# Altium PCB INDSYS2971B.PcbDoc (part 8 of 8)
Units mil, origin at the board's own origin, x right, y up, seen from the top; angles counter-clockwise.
Board outline 6450 x 5820 mil, 6 copper layers (Top Layer, Int1 (PGND), Int2 (AGND), Int3 (Signal), Int4 (PGND), Bottom Layer), stack 70.536 mil thick; 787 components, 431 nets, 2530 pads, 2497 vias.
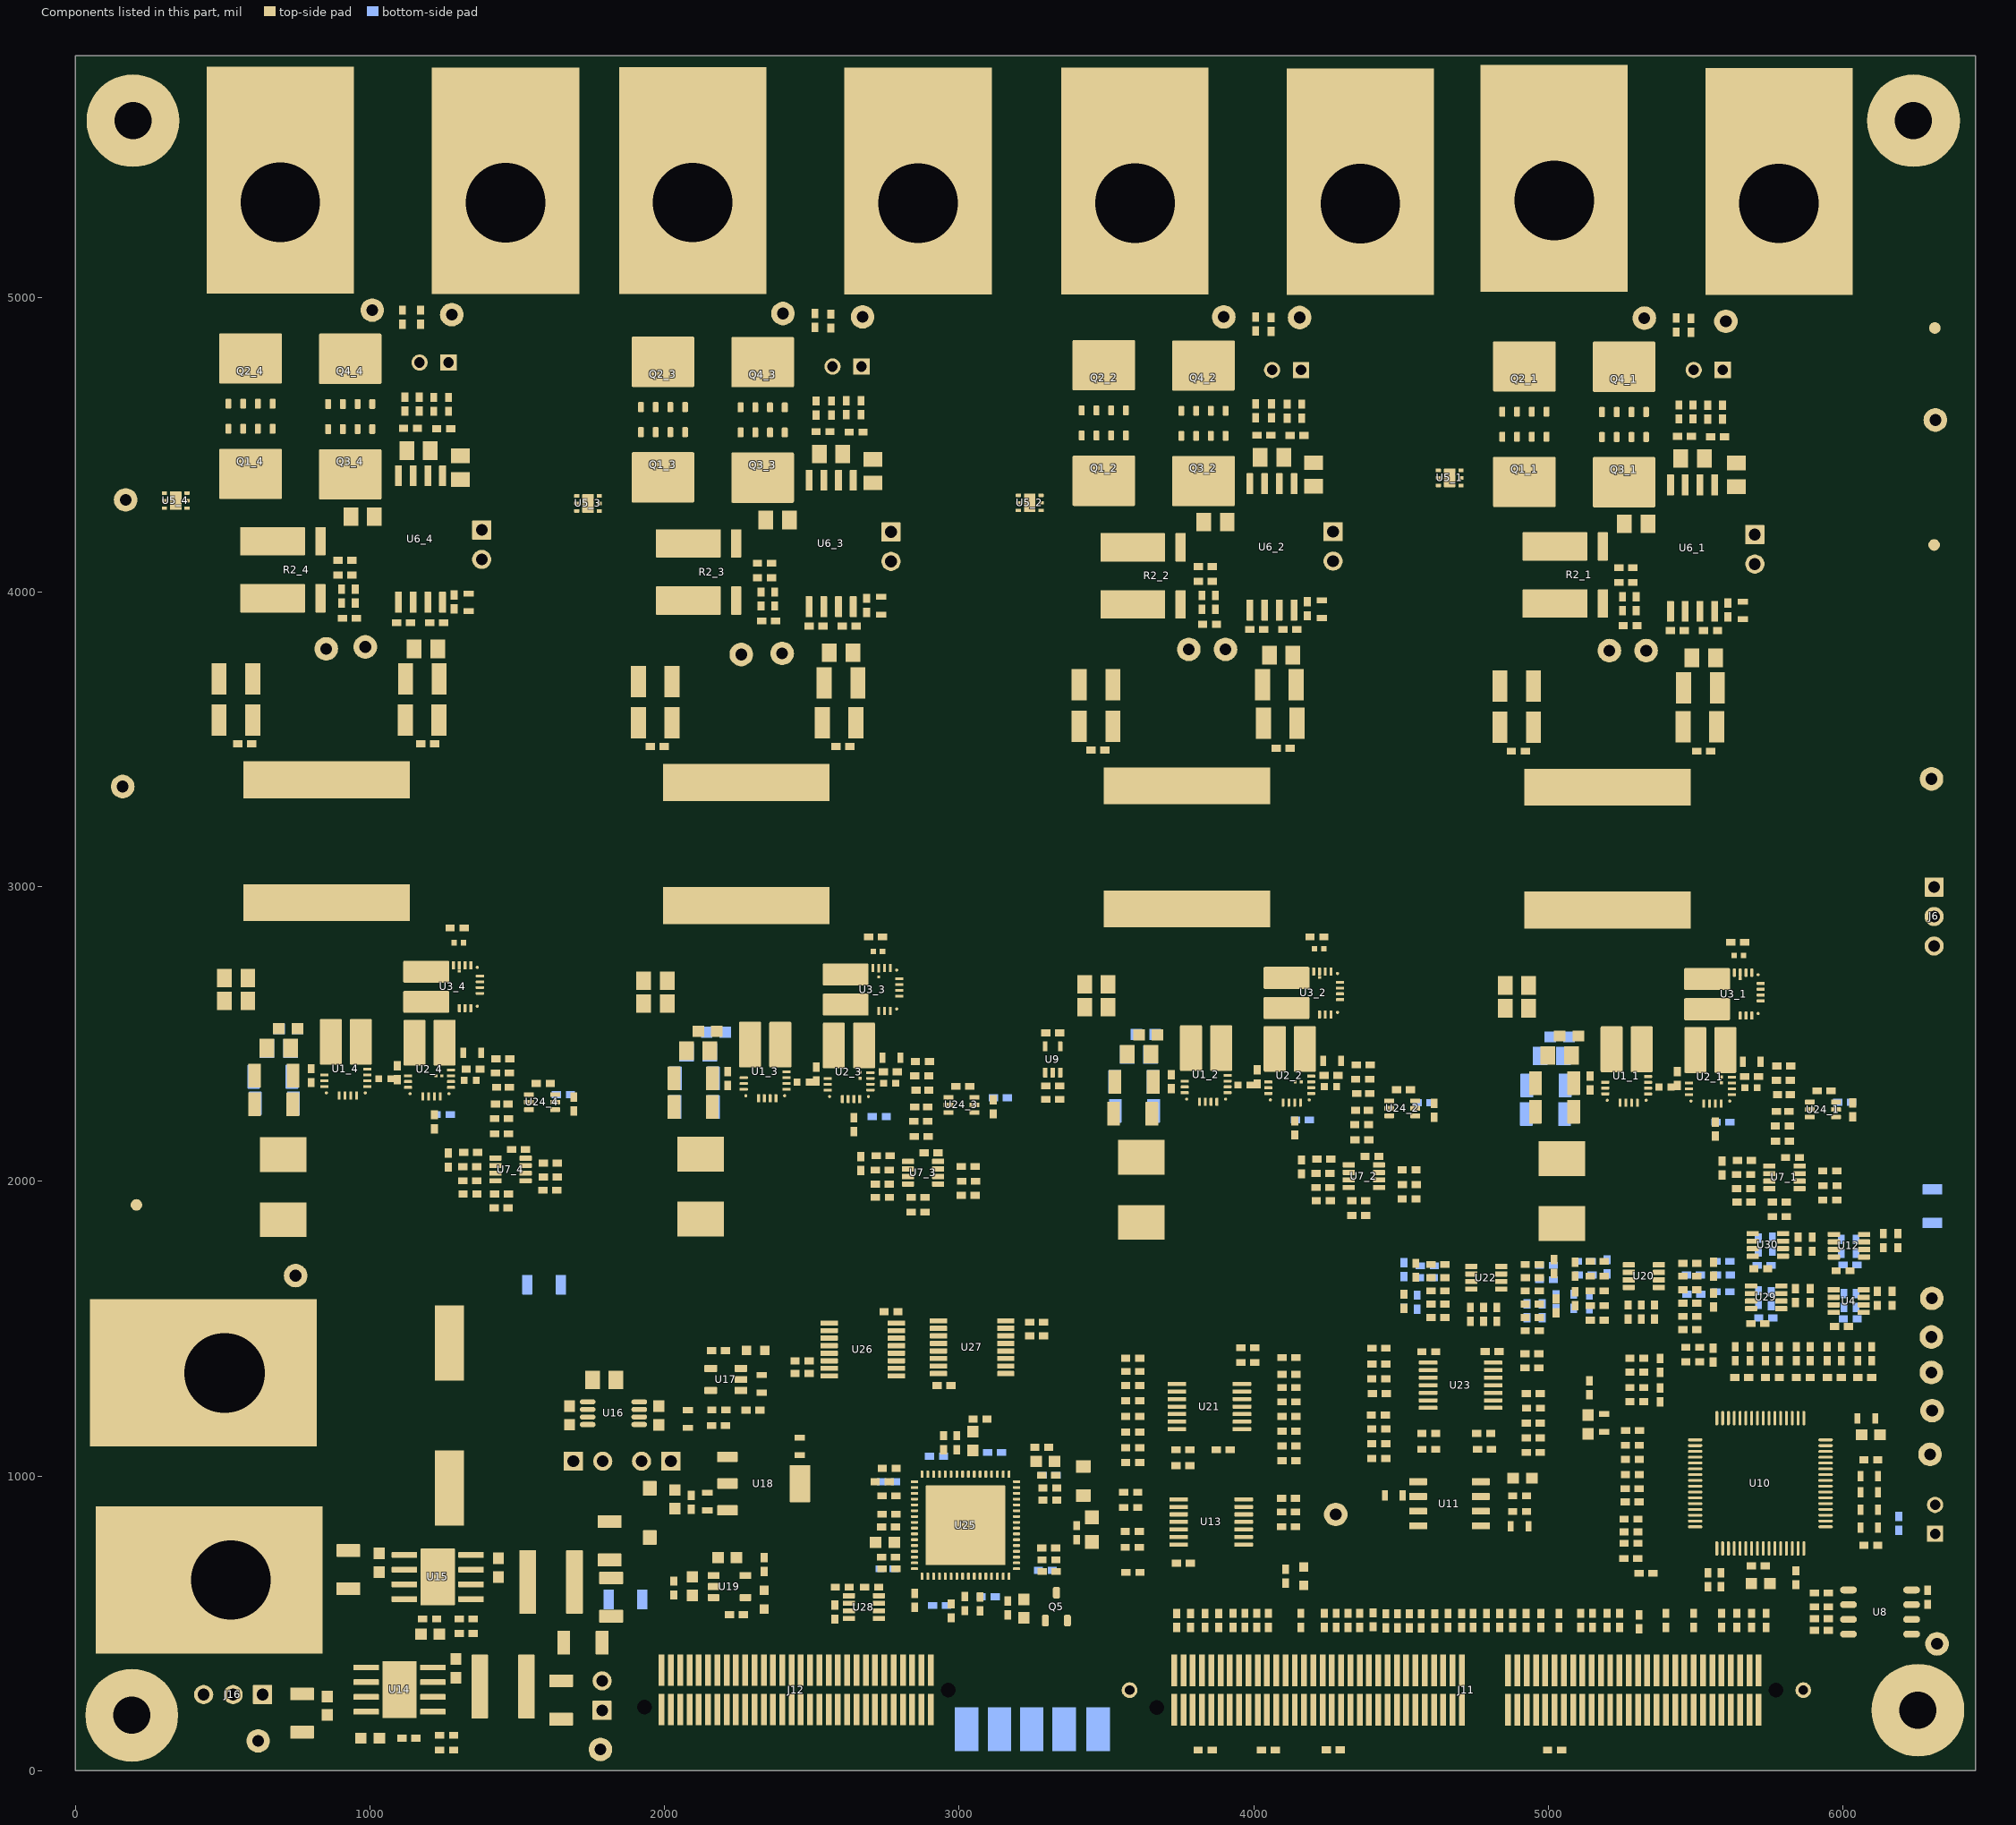
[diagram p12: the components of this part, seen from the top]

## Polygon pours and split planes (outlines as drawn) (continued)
V_HV_3 on Top Layer "TOP_LAYER_V_HV_3_P382" (solid, remove dead copper, pour order 382): 25 vertices, not listed, extent 1778.93,1945.87 2593.62,2540.85
Source_3 on Top Layer "TOP_LAYER_SOURCE_3_P397" (solid, remove dead copper, pour order 397): 1775.39,4685.87 2440.84,4685.87 2440.84,4491.54 1775.39,4491.54
BATP_3 on Top Layer "TOP_LAYER_BATP_3_P400" (solid, remove dead copper, pour order 400): 2455.39,4695.87 1775.39,4695.87 1775.39,5784.26 2455.39,5784.26
SW_2 on Top Layer "TOP_LAYER_SW_2_P380" (solid, remove dead copper, pour order 380): 23 vertices, not listed, extent 3275.54,2344.14 4211.89,3185.33
V_HV_2 on Top Layer "TOP_LAYER_V_HV_2_P384" (solid, remove dead copper, pour order 384): 25 vertices, not listed, extent 3275.54,1934.14 4090.23,2529.12
NetC11_2_1 on Top Layer "TOP_LAYER_NETC11_2_1_P389" (solid, remove dead copper, pour order 389): 3761.01,4033.91 3761.01,3833 4102.11,3833 4102.11,3717.11 4102.11,3193 3275.54,3193 3275.54,3423 3461.42,3423 3481.62,3443.2 3481.62,3747.29 3275.54,3747.29 3275.54,4033.91
Source_2 on Top Layer "TOP_LAYER_SOURCE_2_P398" (solid, remove dead copper, pour order 398): 3272,4674.14 3937.44,4674.14 3937.44,4479.81 3272,4479.81
BATP_2 on Top Layer "TOP_LAYER_BATP_2_P403" (solid, remove dead copper, pour order 403): 3952,4684.14 3272,4684.14 3272,5772.53 3952,5772.53
OUTP2 on Top Layer "TOP_LAYER_OUTP2_P394" (solid, remove dead copper, pour order 394): 3734.05,4197.88 3882.13,4197.88 3884.05,4207.13 3882.13,4207.9 3882.13,4467.75 3877.13,4472.75 3272,4472.75 3272,4047.75 3734.05,4047.75
OUTP1 on Top Layer "TOP_LAYER_OUTP1_P390" (solid, remove dead copper, pour order 390): 5162.05,4193.88 5310.13,4193.88 5312.05,4203.13 5310.13,4203.9 5310.13,4463.75 5305.13,4468.75 4700,4468.75 4700,4043.75 5162.05,4043.75
BATP_1 on Top Layer "TOP_LAYER_BATP_1_P399" (solid, remove dead copper, pour order 399): 5380,4680.14 4700,4680.14 4700,5768.53 5380,5768.53
NetC11_1_1 on Top Layer "TOP_LAYER_NETC11_1_1_P385" (solid, remove dead copper, pour order 385): 5189.01,4029.91 5189.01,3829 5530.11,3829 5530.11,3713.11 5530.11,3189 4703.54,3189 4703.54,3419 4889.42,3419 4909.62,3439.2 4909.62,3743.29 4703.54,3743.29 4703.54,4029.91
V_HV_1 on Top Layer "TOP_LAYER_V_HV_1_P381" (solid, remove dead copper, pour order 381): 25 vertices, not listed, extent 4703.54,1930.14 5518.23,2525.12
SW_1 on Top Layer "TOP_LAYER_SW_1_P377" (solid, remove dead copper, pour order 377): 23 vertices, not listed, extent 4700,2332.76 5636.35,3173.94
NetC11_3_1 on Bottom Layer "BOTTOM_LAYER_NETC11_3_1_P409" (solid, remove dead copper, pour order 409): 2263.78,4046.26 2263.78,3845.35 2604.88,3845.35 2604.88,3729.46 2604.88,3205.35 1778.31,3205.35 1778.31,3435.35 1964.19,3435.35 1984.39,3455.55 1984.39,3759.64 1778.31,3759.64 1778.31,4046.26
AGND on Bottom Layer "BOTTOM_LAYER_AGND_P498" (solid, remove dead copper, pour order 498): 1571.84,39.35 1571.84,71.66 1571.84,1929.41 6350.52,1929.41 6380,1899.93 6380,50.14
5VA on Bottom Layer "BOTTOM_LAYER_5VA_P410" (solid, remove dead copper, pour order 410): 2513.03,647.11 2546.26,613.88 2682.91,613.88 2682.91,687.39 2708.21,687.39 2708.21,555.14 2665,511.93 2665,511.52 2585.82,511.52 2547.2,550.14 2513.03,550.14
AGND on Bottom Layer "BOTTOM_LAYER_AGND_P500" (solid, remove dead copper, pour order 500): 1571.84,39.35 1571.84,71.66 1571.84,1929.41 6350.52,1929.41 6380,1899.93 6380,50.14
PGND on Bottom Layer "BOTTOM_LAYER_PGND_P499" (solid, remove dead copper, pour order 499): 42.17,40.14 1862.17,40.14 1862.17,927.04 1830.13,959.08 1631.15,959.08 1588.55,1001.68 1592.89,1006.03 1592.89,1902.34 6399.97,1902.34 6401.97,1900.35 6401.97,5770.82 42.84,5770.82 42.17,5770.14
PGND on Bottom Layer "BOTTOM_LAYER_PGND_P427" (solid, remove dead copper, pour order 427): 18 vertices, not listed, extent 1056.38,2331.49 1676.69,5779.54
PGND on Bottom Layer "BOTTOM_LAYER_PGND_P426" (solid, remove dead copper, pour order 426): 18 vertices, not listed, extent 5405,2306.49 6025.31,5754.54
OUTP1 on Bottom Layer "BOTTOM_LAYER_OUTP1_P437" (solid, remove dead copper, pour order 437): 5148.25,4188.53 5296.33,4188.53 5296.33,4188.66 5301.34,4193.67 5296.33,4198.69 5296.33,4458.53 5291.33,4463.53 4696.2,4463.53 4696.2,4038.53 5148.25,4038.53
OUTP3 on Bottom Layer "BOTTOM_LAYER_OUTP3_P435" (solid, remove dead copper, pour order 435): 2283.64,4204.14 2431.72,4204.14 2431.72,4204.27 2436.73,4209.28 2431.72,4214.29 2431.72,4474.14 2426.72,4479.14 1831.59,4479.14 1831.59,4054.14 2283.64,4054.14
PGND on Bottom Layer "BOTTOM_LAYER_PGND_P425" (solid, remove dead copper, pour order 425): 18 vertices, not listed, extent 2540.39,2322.1 3160.71,5770.14
PGND on Bottom Layer "BOTTOM_LAYER_PGND_P428" (solid, remove dead copper, pour order 428): 18 vertices, not listed, extent 3931.8,2335.49 4552.12,5783.54
V_HV_2 on Bottom Layer "BOTTOM_LAYER_V_HV_2_P494" (solid, remove dead copper, pour order 494): 25 vertices, not listed, extent 3275.54,1932.73 4090.23,2527.71
NetC11_4_1 on Bottom Layer "BOTTOM_LAYER_NETC11_4_1_P417" (solid, remove dead copper, pour order 417): 863.73,4048.07 863.73,3847.16 1164.9,3847.16 1164.9,3207.16 378.25,3207.16 378.25,3437.16 564.14,3437.16 584.34,3457.36 584.34,3761.45 378.25,3761.45 378.25,4048.07
V_HV_4 on Bottom Layer "BOTTOM_LAYER_V_HV_4_P491" (solid, remove dead copper, pour order 491): 25 vertices, not listed, extent 372.33,1945.13 1187.02,2540.11
OUTP4 on Bottom Layer "BOTTOM_LAYER_OUTP4_P438" (solid, remove dead copper, pour order 438): 823.25,4213.53 971.33,4213.53 971.33,4213.66 976.34,4218.67 971.33,4223.69 971.33,4483.53 966.33,4488.53 371.2,4488.53 371.2,4063.53 823.25,4063.53
Source_4 on Bottom Layer "BOTTOM_LAYER_SOURCE_4_P432" (solid, remove dead copper, pour order 432): 371.2,4682.48 1026.64,4682.48 1026.64,4511.84 371.2,4511.84
BATP_4 on Bottom Layer "BOTTOM_LAYER_BATP_4_P423" (solid, remove dead copper, pour order 423): 1051.2,4692.16 371.2,4692.16 371.2,5782.95 1051.2,5782.95
SW_4 on Bottom Layer "BOTTOM_LAYER_SW_4_P414" (solid, remove dead copper, pour order 414): 23 vertices, not listed, extent 372.33,2354.48 1308.68,3195.66
NetC11_1_1 on Bottom Layer "BOTTOM_LAYER_NETC11_1_1_P418" (solid, remove dead copper, pour order 418): 5188.73,4023.07 5188.73,3822.16 5489.9,3822.16 5489.9,3182.16 4703.25,3182.16 4703.25,3412.16 4889.14,3412.16 4909.34,3432.36 4909.34,3736.45 4703.25,3736.45 4703.25,4023.07
Source_3 on Bottom Layer "BOTTOM_LAYER_SOURCE_3_P431" (solid, remove dead copper, pour order 431): 4696.2,4657.48 5351.64,4657.48 5351.64,4486.84 4696.2,4486.84
BATP_3 on Bottom Layer "BOTTOM_LAYER_BATP_3_P422" (solid, remove dead copper, pour order 422): 5376.2,4667.16 4696.2,4667.16 4696.2,5757.95 5376.2,5757.95
SW_3 on Bottom Layer "BOTTOM_LAYER_SW_3_P412" (solid, remove dead copper, pour order 412): 23 vertices, not listed, extent 1832.72,2345.09 2769.07,3186.27
BATP_3 on Bottom Layer "BOTTOM_LAYER_BATP_3_P421" (solid, remove dead copper, pour order 421): 2511.59,4682.77 1831.59,4682.77 1831.59,5773.55 2511.59,5773.55
Source_3 on Bottom Layer "BOTTOM_LAYER_SOURCE_3_P430" (solid, remove dead copper, pour order 430): 1831.59,4673.09 2487.03,4673.09 2487.03,4502.45 1831.59,4502.45
V_HV_3 on Bottom Layer "BOTTOM_LAYER_V_HV_3_P490" (solid, remove dead copper, pour order 490): 25 vertices, not listed, extent 1785.04,1948.12 2599.73,2543.1
SW_2 on Bottom Layer "BOTTOM_LAYER_SW_2_P415" (solid, remove dead copper, pour order 415): 23 vertices, not listed, extent 3275,2348.94 4211.35,3190.12
BATP_2 on Bottom Layer "BOTTOM_LAYER_BATP_2_P424" (solid, remove dead copper, pour order 424): 3940,4689.47 3260,4689.47 3260,5777.85 3940,5777.85
Source_2 on Bottom Layer "BOTTOM_LAYER_SOURCE_2_P434" (solid, remove dead copper, pour order 434): 3275,4665.47 3930.44,4665.47 3930.44,4494.82 3275,4494.82
OUTP2 on Bottom Layer "BOTTOM_LAYER_OUTP2_P439" (solid, remove dead copper, pour order 439): 3727.05,4197.64 3875.13,4197.64 3875.13,4197.77 3880.15,4202.79 3875.13,4207.8 3875.13,4467.64 3870.13,4472.64 3275,4472.64 3275,4047.64 3727.05,4047.64
NetC11_2_1 on Bottom Layer "BOTTOM_LAYER_NETC11_2_1_P419" (solid, remove dead copper, pour order 419): 3760.48,4043.46 3760.48,3842.54 4061.64,3842.54 4061.64,3202.54 3275,3202.54 3275,3432.54 3460.89,3432.54 3481.09,3452.75 3481.09,3756.83 3275,3756.83 3275,4043.46
V_HV_1 on Bottom Layer "BOTTOM_LAYER_V_HV_1_P454" (solid, remove dead copper, pour order 454): 25 vertices, not listed, extent 4706.13,1928.12 5520.83,2523.1
Source_1 on Bottom Layer "BOTTOM_LAYER_SOURCE_1_P429" (solid, remove dead copper, pour order 429): 4705,4665.47 5360.44,4665.47 5360.44,4494.82 4705,4494.82
BATP_1 on Bottom Layer "BOTTOM_LAYER_BATP_1_P420" (solid, remove dead copper, pour order 420): 5385,4675.14 4705,4675.14 4705,5765.93 5385,5765.93
SW_1 on Bottom Layer "BOTTOM_LAYER_SW_1_P411" (solid, remove dead copper, pour order 411): 23 vertices, not listed, extent 4712.06,2334.45 5648.41,3175.64
AGND on Int2 (AGND) "INT2_(AGND)_AGND_P478" (solid, remove dead copper, pour order 478): 70,50.14 70,5779.54 6399.39,5779.54 6400,5780.14 6400,50.14
V_HV_3 on Int2 (AGND) "INT2_(AGND)_V_HV_3_P470" (solid, remove dead copper, pour order 470): 25 vertices, not listed, extent 1787.89,1945.87 2602.58,2540.85
V_HV_4 on Int2 (AGND) "INT2_(AGND)_V_HV_4_P379" (solid, remove dead copper, pour order 379): 25 vertices, not listed, extent 378.54,1955.27 1193.23,2550.24
SW_4 on Int2 (AGND) "INT2_(AGND)_SW_4_P375" (solid, remove dead copper, pour order 375): 23 vertices, not listed, extent 378.54,2365.27 1314.89,3206.45
SW_3 on Int2 (AGND) "INT2_(AGND)_SW_3_P459" (solid, remove dead copper, pour order 459): 23 vertices, not listed, extent 1778.93,2353.16 2715.28,3194.35
V_HV_2 on Int2 (AGND) "INT2_(AGND)_V_HV_2_P455" (solid, remove dead copper, pour order 455): 25 vertices, not listed, extent 3277.5,1933.74 4092.2,2528.72
SW_2 on Int2 (AGND) "INT2_(AGND)_SW_2_P449" (solid, remove dead copper, pour order 449): 23 vertices, not listed, extent 3275.54,2345.23 4211.89,3186.42
V_HV_1 on Int2 (AGND) "INT2_(AGND)_V_HV_1_P446" (solid, remove dead copper, pour order 446): 25 vertices, not listed, extent 4710,1938.12 5524.69,2533.1
SW_1 on Int2 (AGND) "INT2_(AGND)_SW_1_P444" (solid, remove dead copper, pour order 444): 23 vertices, not listed, extent 4700,2328.96 5636.35,3170.14
V_HV_3 on Int3 (Signal) "INT3_(SIGNAL)_V_HV_3_P469" (solid, remove dead copper, pour order 469): 25 vertices, not listed, extent 1787.89,1943.03 2602.58,2538.01
V_HV_4 on Int3 (Signal) "INT3_(SIGNAL)_V_HV_4_P466" (solid, remove dead copper, pour order 466): 25 vertices, not listed, extent 378.54,1956.52 1193.23,2551.49
SW_4 on Int3 (Signal) "INT3_(SIGNAL)_SW_4_P461" (solid, remove dead copper, pour order 461): 23 vertices, not listed, extent 378.54,2355.27 1314.89,3196.45
SW_3 on Int3 (Signal) "INT3_(SIGNAL)_SW_3_P458" (solid, remove dead copper, pour order 458): 23 vertices, not listed, extent 1778.93,2356.25 2715.28,3197.44
V_HV_2 on Int3 (Signal) "INT3_(SIGNAL)_V_HV_2_P453" (solid, remove dead copper, pour order 453): 25 vertices, not listed, extent 3277.5,1934.14 4092.2,2529.12
SW_2 on Int3 (Signal) "INT3_(SIGNAL)_SW_2_P450" (solid, remove dead copper, pour order 450): 23 vertices, not listed, extent 3265.54,2345.23 4201.89,3186.42
V_HV_1 on Int3 (Signal) "INT3_(SIGNAL)_V_HV_1_P445" (solid, remove dead copper, pour order 445): 25 vertices, not listed, extent 4705.04,1935.8 5519.73,2530.78
SW_1 on Int3 (Signal) "INT3_(SIGNAL)_SW_1_P443" (solid, remove dead copper, pour order 443): 23 vertices, not listed, extent 4700,2328.92 5636.35,3170.1
AGND on Int4 (PGND) "INT4_(PGND)_AGND_P492" (solid, remove dead copper, pour order 492): 1578.15,37.52 1578.15,69.83 1578.15,1927.58 6356.83,1927.58 6386.31,1898.1 6386.31,48.31
PGND on Int4 (PGND) "INT4_(PGND)_PGND_P489" (solid, remove dead copper, pour order 489): 17 vertices, not listed, extent 40,39.35 6399.8,5770.02
Source_1 on Int4 (PGND) "INT4_(PGND)_SOURCE_1_P395" (solid, remove dead copper, pour order 395): 4700,4670.27 5365.44,4670.27 5365.44,4475.94 4700,4475.94
Source_2 on Int4 (PGND) "INT4_(PGND)_SOURCE_2_P483" (solid, remove dead copper, pour order 483): 3272.39,4681.15 3937.83,4681.15 3937.83,4486.82 3272.39,4486.82
Source_3 on Int4 (PGND) "INT4_(PGND)_SOURCE_3_P482" (solid, remove dead copper, pour order 482): 1780.39,4689 2445.84,4689 2445.84,4494.67 1780.39,4494.67
Source_4 on Int4 (PGND) "INT4_(PGND)_SOURCE_4_P396" (solid, remove dead copper, pour order 396): 375,4695.27 1040.44,4695.27 1040.44,4500.94 375,4500.94
V_HV_3 on Int4 (PGND) "INT4_(PGND)_V_HV_3_P471" (solid, remove dead copper, pour order 471): 25 vertices, not listed, extent 1778.93,1948.47 2593.62,2543.45
V_HV_4 on Int4 (PGND) "INT4_(PGND)_V_HV_4_P465" (solid, remove dead copper, pour order 465): 25 vertices, not listed, extent 378.54,1955.85 1193.23,2550.82
SW_4 on Int4 (PGND) "INT4_(PGND)_SW_4_P460" (solid, remove dead copper, pour order 460): 23 vertices, not listed, extent 385.22,2352.61 1321.57,3193.8
SW_3 on Int4 (PGND) "INT4_(PGND)_SW_3_P457" (solid, remove dead copper, pour order 457): 23 vertices, not listed, extent 1778.93,2356.25 2715.28,3197.44
V_HV_2 on Int4 (PGND) "INT4_(PGND)_V_HV_2_P440" (solid, remove dead copper, pour order 440): 25 vertices, not listed, extent 3275,1944.13 4089.69,2539.11
SW_2 on Int4 (PGND) "INT4_(PGND)_SW_2_P451" (solid, remove dead copper, pour order 451): 23 vertices, not listed, extent 3265.54,2345.23 4201.89,3186.42
V_HV_1 on Int4 (PGND) "INT4_(PGND)_V_HV_1_P436" (solid, remove dead copper, pour order 436): 25 vertices, not listed, extent 4705.04,1928.12 5519.73,2523.1
SW_1 on Int4 (PGND) "INT4_(PGND)_SW_1_P442" (solid, remove dead copper, pour order 442): 23 vertices, not listed, extent 4700,2338.96 5636.35,3180.14
AGND on Int1 (PGND) "INT1_(PGND)_AGND_P496" (solid, remove dead copper, pour order 496): 1571.84,39.35 1571.84,71.66 1571.84,1929.41 6350.52,1929.41 6380,1899.93 6380,50.14
PGND on Int1 (PGND) "INT1_(PGND)_PGND_P493" (solid, remove dead copper, pour order 493): 40,41.99 1860,41.99 1860,928.88 1827.96,960.93 1628.98,960.93 1586.38,1003.53 1590.72,1007.87 1590.72,1904.18 6397.8,1904.18 6399.8,1902.19 6399.8,5772.66 40.67,5772.66 40,5771.99
V_HV on Int1 (PGND) "INT1_(PGND)_V_HV_P488" (solid, remove dead copper, pour order 488): 17 vertices, not listed, extent 45,1094.88 5509.81,1919.88
Source_1 on Int1 (PGND) "INT1_(PGND)_SOURCE_1_P393" (solid, remove dead copper, pour order 393): 4700,4670.14 5365.44,4670.14 5365.44,4475.81 4700,4475.81
Source_2 on Int1 (PGND) "INT1_(PGND)_SOURCE_2_P484" (solid, remove dead copper, pour order 484): 3272,4674.14 3937.44,4674.14 3937.44,4479.81 3272,4479.81
Source_3 on Int1 (PGND) "INT1_(PGND)_SOURCE_3_P481" (solid, remove dead copper, pour order 481): 1780.39,4689 2445.84,4689 2445.84,4494.67 1780.39,4494.67
Source_4 on Int1 (PGND) "INT1_(PGND)_SOURCE_4_P480" (solid, remove dead copper, pour order 480): 375,4698.87 1040.44,4698.87 1040.44,4504.54 375,4504.54
V_HV_3 on Int1 (PGND) "INT1_(PGND)_V_HV_3_P468" (solid, remove dead copper, pour order 468): 25 vertices, not listed, extent 1778.93,1944.45 2593.62,2539.43
V_HV_4 on Int1 (PGND) "INT1_(PGND)_V_HV_4_P467" (solid, remove dead copper, pour order 467): 25 vertices, not listed, extent 388.54,1952.28 1203.23,2547.26
SW_4 on Int1 (PGND) "INT1_(PGND)_SW_4_P463" (solid, remove dead copper, pour order 463): 23 vertices, not listed, extent 380,2358.96 1316.35,3200.14
SW_3 on Int1 (PGND) "INT1_(PGND)_SW_3_P456" (solid, remove dead copper, pour order 456): 23 vertices, not listed, extent 1778.93,2357.75 2715.28,3198.93
V_HV_2 on Int1 (PGND) "INT1_(PGND)_V_HV_2_P452" (solid, remove dead copper, pour order 452): 25 vertices, not listed, extent 3277.5,1933.35 4092.2,2528.33
SW_2 on Int1 (PGND) "INT1_(PGND)_SW_2_P448" (solid, remove dead copper, pour order 448): 23 vertices, not listed, extent 3265.54,2345.04 4201.89,3186.22
V_HV_1 on Int1 (PGND) "INT1_(PGND)_V_HV_1_P447" (solid, remove dead copper, pour order 447): 25 vertices, not listed, extent 4710,1938.12 5524.69,2533.1
SW_1 on Int1 (PGND) "INT1_(PGND)_SW_1_P407" (solid, remove dead copper, pour order 407): 23 vertices, not listed, extent 4697.33,2329.48 5633.68,3170.66

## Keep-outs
Keep-Out Layer:
  text ".Layer_Name" at -153,-843.35 h60

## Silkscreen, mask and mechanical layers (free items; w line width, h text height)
Top Overlay:
  drawing of 158 lines, arcs and shapes, not listed
  text "ch2" at 4014.57,5555.55 h60 r90
  text "ch4" at 1111.9,5547.14 h60 r90
  text "ch3" at 2532.77,5537.16 h60 r90
  text "ch1" at 5451.89,5532.14 h60 r90
  text "BAT-" at 2598.39,5299.23 h60 r90
  text "BAT-" at 1173,5282 h60 r90
  text "BAT+" at 2453,5281.46 h60 r90
  text "BAT+" at 1039.2,5277 h60 r90
  text "BAT-" at 5523,5260.22 h60 r90
  text "BAT+" at 5378,5252.14 h60 r90
  text "BAT+" at 3970,5245.66 h60 r90
  text "BAT-" at 4069.06,5245.66 h60 r90
  text "H*" at 5616.2,3375.03 h30
  text "H*" at 5464.89,1767.16 h30
  text "Vin+" at 888,1262 h60 r90
  text "PGND-" at 913.79,797 h60 r90
Bottom Solder:
  text ".Layer_Name" at 1563.57,5973.25 h60
  text ".Layer_Name" at 3023.97,5963.86 h60
  text ".Layer_Name" at 5888.57,5948.25 h60
M1 Board Outline:
  lines w10: 0,0 0,5830 6450,5830 6450,0 0,0
  text ".Layer_Name" at -153,-843.35 h60
M2 Board Dimensions:
  rectangle: -1230,-1147.43 -855,-1022.43
  rectangle: -1244,-1390.36 -1119,-1265.36
  lines w7: -1244,-1515.36 -1244,-1265.36 ; -1119,-1515.36 -1119,-1265.36 ; -994,-1515.36 -994,-1265.36 ; -744,-1515.36 -744,-1265.36
  text ".Layer_Name" at -153,-843.35 h60
M3 3D STEP Top:
  text ".Layer_Name" at -153,-843.35 h60
M4 3D STEP Bottom:
  text ".Layer_Name" at -153,-843.35 h60
M5 Assembly Top:
  lines w10: -1135,-1120 -1135,-510 ; -1022,-915.02 5578,-915.02 ; -1022,-711.69 5580,-711.69 ; -1022,-508.36 -1022,-1118.36 2983,-1118.36 5580,-1118.36 5580,-508.36 -1021.5,-508.36 ; 324.5,-1395 1900,-1395 ; 1443,-1118.36 1443,-508.36 ; 2040,-1518.86 3615.5,-1518.86 ; 2615,-1405 4190.5,-1405 ; 2710,-711.69 2710,-508.36 ; 3550,-711.69 3550,-508.36 ; 4172,-1124.86 4172,-922.02
  text "COMPONENTS MARKED 'DNP' SHOULD NOT BE POPULATED." at 423.5,-303.36 h60
  text "ASSEMBLY VARIANT:" at 423,-418.86 h60
  text ".VariantName" at 1459,-418.86 h60
  text "BOARD #:" at 1518,-640.52 h60
  text ".PRJ_Number" at 2063.5,-640.52 h60
  text "REV:" at 2908,-640.52 h60
  text ".PCB_Rev" at 3199.5,-640.52 h60
  text "SVN REV:" at 3746,-640.52 h60
  text ".VersionControl_RevNumber" at 4252,-640.52 h60
  text "PLOT NAME =" at -915,-660 h60
  text "PCB VIEWED FROM TOP SIDE" at -920,-835 h60
  text "TID #:" at 1518,-843.86 h60
  text ".TID" at 2063.5,-843.86 h60
  text ".plot_File_Name" at 2825,-850 h60
  text "GENERATED    :" at 1520,-1049.19 h60
  text ".Print_Date" at 2389.5,-1049.19 h60
  text ".Print_Time" at 3118.5,-1049.19 h60
  text "TEXAS INSTRUMENTS" at 4383,-1049.19 h60
M6 Assembly Bottom:
  lines w10: -1022.5,-712.19 5579.5,-712.19 ; -1020.5,-915.52 5579.5,-915.52 ; 1007.5,-712.19 1007.5,-508.86 ; 1847.5,-712.19 1847.5,-508.86 ; 3114.5,-1118.86 3114.5,-508.86 ; 3562.47,5681.85 3562.47,5884.68 ; 4003.5,-1118.86 5579,-1118.86 5579,-508.86 -1022.5,-508.86 -1022.5,-1118.86 1574.5,-1118.86 5579.5,-1118.86 5579.5,-508.86
  text "COMPONENTS MARKED 'DNP' SHOULD NOT BE POPULATED." at 3390,-320 h60
  text ".VariantName" at 2390,-435 h60
  text "ASSEMBLY VARIANT:" at 3385,-435 h60
  text "SVN REV:" at 811.5,-641.02 h60
  text ".PCB_Rev" at 1358,-641.02 h60
  text "REV:" at 1649.5,-641.02 h60
  text ".PRJ_Number" at 2494,-641.02 h60
  text "BOARD #:" at 3039.5,-641.02 h60
  text "PCB VIEWED FROM BOTTOM SIDE" at 5516,-641.02 h60
  text "TEXAS INSTRUMENTS" at 5520,-835 h60
  text ".plot_File_Name" at 1725,-840 h60
  text ".TID" at 2494,-844.36 h60
  text "TID #:" at 3039.5,-844.36 h60
  text ".VersionControl_RevNumber" at 320,-1025 h60
  text ".Print_Time" at 1439,-1049.69 h60
  text ".Print_Date" at 2168,-1049.69 h60
  text "GENERATED    :" at 3037.5,-1049.69 h60
  text "PLOT NAME =" at 5516,-1049.69 h60
M9 Title Sheet:
  drawing of 55 lines, arcs and shapes, not listed
  text "1" at 9.84,8051.64 h70
  text "2" at 2505.5,8051.64 h70
  text "3" at 4994.84,8051.64 h70
  text "5" at 10000.5,8051.64 h70
  text "6" at 12505.5,8051.64 h70
  text "4" at -1172.14,6999.67 h70
  text "A" at -1146.5,6908.64 h70
  text "A" at 13653.5,6908.64 h70
  text "PROJECT TITLE:" at 12485.5,4775.27 h45
  text ".PRJ_Title" at 12535.5,4641.94 h70
  text "B" at -1146.5,4528.64 h70
  text "B" at 13653.5,4528.64 h70
  text "C" at 13653.5,2153.64 h70
  text "DESIGNED FOR:" at 10613.5,-8.36 h45
  text ".PRJ_Customer" at 10663.5,-148.36 h70
  text "D" at 13653.5,-216.36 h70
  text "FILE NAME:" at 10613.5,-308.36 h45
  text ".PCB_File_Name_No_Path" at 10663.5,-428.36 h70
  text "Texas Instruments (TI) and/or its licensors do not warrant the accuracy or completeness of this specification" at 5644,-590.19 h45
  text "ENGINEER:" at 10613.5,-598.36 h45
  text "LAYOUT BY:" at 12118.5,-598.36 h45
  text "or any information contained therein. TI and/or its licensors do not warrant that this design will meet" at 5599.01,-702.86 h45
  text ".PRJ_Engineer" at 10663.5,-753.35 h70
  text ".PCB_Layout" at 12169,-753.35 h70
  text "the specifications, will be suitable for your application or fit for any particular purpose, or will operate in" at 5599.01,-815.52 h45
  text ".Layer_Name" at -153,-843.35 h60
  text "ALTIUM DESIGNER VERSION:" at 12118.5,-908.36 h45
  text "an implementation. TI and/or its licensors do not warrant that the design is production worthy. You should" at 5599.01,-928.19 h45
  text "completely validate and test your design implementation to confirm the system functionality for your application." at 5644,-1040.86 h45
  text ".print_Scale" at 10663.5,-1041.68 h70
  text ".Application_BuildNumber" at 12169,-1041.68 h70
  text "2" at 2505.5,-1248.36 h70
  text "3" at 4994.84,-1248.36 h70
  text "4" at 7501.51,-1248.36 h70
  text "5" at 10000.5,-1248.36 h70
  text "6" at 12505.5,-1248.36 h70
M10 Fab Notes:
  drawing of 189 lines, arcs and shapes, not listed
  text "DESIGN INFORMATION" at 11652.02,6371.32 h60
  text "X" at 5262.55,6255.66 h60
  text "MIN. TRACK WIDTH:" at 11007.46,6239.19 h60
  text "6" at 12103.7,6239.2 h60
  text "MIL" at 12258.46,6239.19 h60
  text "7.874" at 11937.32,6117.51 h60
  text "MIN. CLEARANCE:" at 11007.46,6115.07 h60
  text "MIL" at 12258.46,6115.07 h60
  text "MIN. VIA PAD SIZE:" at 11007.46,5990.94 h60
  text "20" at 12073.71,5990.94 h60
  text "MIL" at 12258.46,5990.94 h60
  text "0.15mm (5.9MIL)" at 11702.46,5861.04 h60
  text "MINIMUM ANNULAR RING" at 10678.23,5852.82 h60
  text "EXTERNAL" at 12410.46,5852.82 h60
  text "PER" at 10878.23,5742.69 h60
  text "IPC-D-275 CLASS 2 LEVEL C" at 11098.23,5742.69 h60
  text "MIL, HOLES" at 12586.46,5642.21 h60
  text "+/-" at 12194,5633.63 h60
  text "+/-" at 13048,5633.63 h60
  text "REGISTRATION TOLERANCES:" at 10678.23,5632.56 h60
  text "METAL" at 11878,5632.56 h60
  text "5" at 12454.2,5632.57 h60
  text "3" at 13287.2,5632.57 h60
  text "MIL" at 13403.46,5632.56 h60
  text "HOLE SIZE TOLERANCE (UNLESS OTHERWISE SPECIFIED):" at 10678.23,5534.25 h60
  text "+/-" at 13048,5531.38 h60
  text "3" at 13287.2,5530.31 h60
  text "MIL" at 13403.46,5530.31 h60
  text "MATERIAL:" at 10603.46,5392.66 h60
  text "FR-4 High Tg" at 11589.9,5264.14 h60
  text "X" at 11444.46,5255.69 h60
  text "FR-408" at 11024.46,5251.63 h60
  text "OTHER" at 12512.46,5251.63 h60
  text "X" at 13433.45,5137.07 h60
  text "X" at 11213.46,5108.69 h60
  text "62 MIL (1.6mm) +/-10%" at 11344.56,5108.6 h60
  text "THICKNESS:" at 10678.23,5100.38 h60
  text "OTHER" at 12629.46,5100.38 h60
  text "TOLERANCE:" at 10678.23,4962.07 h60
  text "ANSI IPC-6012 TYPE 3 CLASS 2" at 11704.48,4962.07 h60
  text "OTHER +/-" at 11704.46,4817.88 h60
  text "BOW & TWIST:" at 10678.23,4672.69 h60
  text "X" at 11526.46,4672.69 h60
  text "ANSI IPC-6012 TYPE 3 CLASS 2" at 11704.48,4672.69 h60
  text "OTHER +/-" at 11704.46,4525.99 h60
  text "DRILLING:" at 10603.46,4395.37 h60
  text "X" at 11338.46,4289.69 h60
  text "NC_DRILL FILES" at 12364.46,4290.18 h60
  text "REFERENCE:" at 10678.23,4286.25 h60
  text "AS SHOWN" at 11513.46,4286.25 h60
  text "OTHER" at 12662.46,4144 h60
  text "X" at 11816.46,4142.69 h60
  text "PTH COPPER THICKNESS:" at 10677.91,4140.47 h60
  text "20-30 um" at 11945.14,4140.47 h60
  text "BOARD FINISH:" at 10603.46,3992.87 h60
  text "X" at 12223.46,3885.69 h60
  text "SILKSCREEN:" at 10758.68,3882.74 h60
  text "TOP" at 11833.46,3882.74 h60
  text "BOTTOM" at 12344.46,3882.74 h60
  text "X" at 11713.46,3876.69 h60
  text "SILKSCREEN COLOR:" at 10758.68,3727.55 h60
  text "X" at 11710.46,3726.69 h60
  text "WHITE" at 11833.46,3727.55 h60
  text "OTHER" at 12344.46,3727.55 h60
  text "X" at 11845.46,3588.69 h60
  text "GREEN" at 11964.46,3584.11 h60
  text "OTHER" at 12582.46,3584.11 h60
  text "SOLDER RESIST COLOR:" at 10758.68,3577.24 h60
  text "MATTE" at 11964.46,3429.85 h60
  text "SEMI-GLOSS" at 12582,3429.22 h60
  text "IMMERSION GOLD (ENIG)" at 11664.46,3257.08 h60
  text "X" at 11476.46,3250.69 h60
  text "ENEPIG" at 13002,3249.86 h60
  text "SURFACE FINISH:" at 10603.46,3248.86 h60
  text "IMM. TIN/SILVER OR EQUIV" at 10933,3111.55 h60
  text "OTHER" at 12364.46,3107.61 h60
  text "ARRAY/PANEL:" at 10603.46,2952.23 h60
  text "CUT AND TRIM PER M1 BOARD OUTLINE" at 11664.46,2944.01 h60
  text "N.C. ROUTE" at 11664.46,2808.04 h60
  text "V. SCORE" at 12530.46,2808.04 h60
  text "CERTIFICATION:" at 10603.46,2678.92 h60
  text "MATERIALS AND WORKMANSHIP FOR ALL PCBS" at 11328.46,2678.92 h60
  text "TO MEET OR EXCEED THE REQUIREMENTS OF:" at 11328.46,2584.85 h60
  text "ANSI IPC-A-600F CLASS ->" at 11093.96,2456.22 h60
  text "2" at 12851.96,2456.22 h60
  text "1" at 12536.96,2454.73 h60
  text "3" at 13205.96,2454.73 h60
  text "X" at 12733.46,2453.69 h60
  text "X" at 10953.46,2447.69 h60
  text "RoHS" at 11905.96,2308.54 h60
  text "OTHER" at 12550.36,2308.54 h60
  text "PER ORDER" at 12947.42,2308.54 h60
  text "ALL BOARDS MUST MEET OR EXCEED UL94-V0 REQUIREMENTS." at 10631,2154.71 h60
  text "PCB MUST BEAR THE UL94V-0 UL REGISTERED MATERIAL ID NUMBER" at 10630,2060 h60
  text "ADDITIONAL REQUIREMENTS:" at 10620,1900 h60
  text "YES" at 11440,1790 h60
  text "MICROSECTION:" at 10640,1775 h60
  text "REQUIRED" at 12397.46,1650.39 h60
  text "X" at 12278.46,1648.31 h60
  text "NONE" at 11935.96,1647.53 h60
  text "PER ORDER" at 12989.46,1647.53 h60
  text "BARE BOARD ELEC. TEST:" at 10640,1635 h60
  text "XX MIL VIAS REQUIRE NON-CONDUCTIVE FILL AND PLANARIZE" at 10795,1410 h59
  text "12.5mil MIL VIAS REQUIRE CONDUCTIVE FILL AND PLANARIZE" at 10795,1340 h60
  text "X" at 10671.31,1324 h60
  text "OUTER XX MIL TRACES REQUIRE 50 OHM SINGLE-ENDED IMPEDANCE" at 10795,1200 h58
  text "LAYER 2 & 3 (INNER LAYERS) XX MIL WIDE, XX MIL SPACE / TRACES REQUIRE 100 OHM DIFFERENTIAL IMPEDANCE" at 10785,955 h60
  text ".Layer_Name" at -153,-843.35 h60
M11 Gerber Information:
  lines w10: -1026,-1121.43 -1026,-511.43 ; -1025.5,-1121.43 -1025.5,-511.43 ; -1022,-1118.36 2983,-1118.36 5580,-1118.36 5580,-508.36 -1021.5,-508.36 ; -1022,-915.02 5578,-915.02 ; -1022,-711.69 5580,-711.69 ; 1443,-1118.36 1443,-508.36 ; 2710,-711.69 2710,-508.36 ; 3550,-711.69 3550,-508.36 ; 4172,-1124.86 4172,-922.02
  text "ALL ARTWORK VIEWED FROM TOP SIDE" at -958.5,-640.52 h60
  text "BOARD #:" at 1518,-640.52 h60
  text ".PRJ_Number" at 2063.5,-640.52 h60
  text "REV:" at 2908,-640.52 h60
  text ".PCB_Rev" at 3199.5,-640.52 h60
  text "SVN REV:" at 3746,-640.52 h60
  text ".VersionControl_RevNumber" at 4252,-640.52 h60
  text "TID #:" at 1518,-843.86 h60
  text ".TID" at 2063.5,-843.86 h60
  text "LAYER NAME =" at -962.5,-846.42 h60
  text ".plot_File_Name" at -153,-1049.19 h60
  text "GENERATED    :" at 1520,-1049.19 h60
  text ".Print_Date" at 2389.5,-1049.19 h60
  text ".Print_Time" at 3118.5,-1049.19 h60
  text "TEXAS INSTRUMENTS" at 4383,-1049.19 h60
  text "PLOT NAME =" at -962.5,-1052.26 h60
M12 Stackup:
  drawing of 503 lines, arcs and shapes, not listed
  text "Layer" at 5940.53,8830.01 h60
  text "Name" at 6350.44,8830.01 h60
  text "Material" at 7680.06,8830.01 h60
  text "Thickness" at 8279.91,8830.01 h60
  text "Constant" at 8929.74,8830.01 h60
  text "Board Layer Stack" at 9499.6,8830.01 h60
  text "Top Overlay" at 6350.44,8710.01 h60
  text "Top Solder" at 6350.44,8590.01 h60
  text "SM-001" at 7680.06,8590.01 h60
  text "1.00mil" at 8279.91,8590.01 h60
  text "4" at 8929.74,8590.01 h60
  text "Top Surface Finish" at 6350.44,8470.01 h60
  text "PbSn" at 7680.06,8470.01 h60
  text "0.79mil" at 8279.91,8470.01 h60
  text "1" at 5940.53,8350.01 h60
  text "Top Layer" at 6350.44,8350.01 h60
  text "CF-005" at 7680.06,8350.01 h60
  text "2.76mil" at 8279.91,8350.01 h60
  text "Dielectric 6" at 6350.44,8230.01 h60
  text "PP-006" at 7680.06,8230.01 h60
  text "2.80mil" at 8279.91,8230.01 h60
  text "4.1" at 8929.74,8230.01 h60
  text "Dielectric 1" at 6350.44,8110.01 h60
  text "PP-017" at 7680.06,8110.01 h60
  text "5.10mil" at 8279.91,8110.01 h60
  text "4.3" at 8929.74,8110.01 h60
  text "2" at 5940.53,7990.01 h60
  text "Int1 (PGND)" at 6350.44,7990.01 h60
  text "CF-005" at 7680.06,7990.01 h60
  text "2.76mil" at 8279.91,7990.01 h60
  text "Dielectric 2" at 6350.44,7870.01 h60
  text "PP-017" at 7680.06,7870.01 h60
  text "5.10mil" at 8279.91,7870.01 h60
  text "4.3" at 8929.74,7870.01 h60
  text "3" at 5940.53,7750.01 h60
  text "Int2 (AGND)" at 6350.44,7750.01 h60
  text "CF-005" at 7680.06,7750.01 h60
  text "2.76mil" at 8279.91,7750.01 h60
  text "Dielectric 3" at 6350.44,7630.01 h60
  text "Core-039" at 7680.06,7630.01 h60
  text "28.00mil" at 8279.91,7630.01 h60
  text "4.8" at 8929.74,7630.01 h60
  text "4" at 5940.53,7510.01 h60
  text "Int3 (Signal)" at 6350.44,7510.01 h60
  text "CF-005" at 7680.06,7510.01 h60
  text "2.76mil" at 8279.91,7510.01 h60
  text "Dielectric 4" at 6350.44,7390.01 h60
  text "PP-017" at 7680.06,7390.01 h60
  text "5.10mil" at 8279.91,7390.01 h60
  text "4.3" at 8929.74,7390.01 h60
  text "5" at 5940.53,7270.01 h60
  text "Int4 (PGND)" at 6350.44,7270.01 h60
  text "CF-005" at 7680.06,7270.01 h60
  text "2.76mil" at 8279.91,7270.01 h60
  text "Dielectric 5" at 6350.44,7150.01 h60
  text "PP-017" at 7680.06,7150.01 h60
  text "5.10mil" at 8279.91,7150.01 h60
  text "4.3" at 8929.74,7150.01 h60
  text "Dielectric 7" at 6350.44,7030.01 h60
  text "PP-006" at 7680.06,7030.01 h60
  text "2.80mil" at 8279.91,7030.01 h60
  text "4.1" at 8929.74,7030.01 h60
  text "6" at 5940.53,6910.01 h60
  text "Bottom Layer" at 6350.44,6910.01 h60
  text "CF-005" at 7680.06,6910.01 h60
  text "2.76mil" at 8279.91,6910.01 h60
  text "Bottom Surface Finish" at 6350.44,6790.01 h60
  text "PbSn" at 7680.06,6790.01 h60
  text "0.79mil" at 8279.91,6790.01 h60
  text "Bottom Solder" at 6350.44,6670.01 h60
  text "SM-001" at 7680.06,6670.01 h60
  text "1.00mil" at 8279.91,6670.01 h60
  text "4" at 8929.74,6670.01 h60
  text "Bottom Overlay" at 6350.44,6550.01 h60
  text ".Layer_Name" at 130,-840 h60
M13 Component Bodies Top:
  text ".Layer_Name" at -153,-843.35 h60
M14 Component Bodies Bottom:
  text ".Layer_Name" at -153,-843.35 h60
M15 Courtyards Top:
  text ".Layer_Name" at -153,-843.35 h60
M16 Courtyards Bottom:
  text ".Layer_Name" at -153,-843.35 h60
Drill Drawing:
  circle w10: c-821.54,6785.28 r27.63
  lines w10: -849.17,6881.97 -821.54,6895.78 -793.92,6881.97 -807.73,6909.6 -793.92,6937.22 -821.54,6923.41 -849.17,6937.22 -835.36,6909.6 -849.17,6881.97 ; -849.17,7020.1 -835.36,7020.1 -835.36,7006.29 -807.73,7006.29 -807.73,7020.1 -793.92,7020.1 -793.92,7047.73 -807.73,7047.73 -807.73,7061.54 -835.36,7061.54 -835.36,7047.73 -849.17,7047.73 -849.17,7020.1 ; -849.17,7130.61 -793.92,7130.61 -793.92,7185.86 -849.17,7185.86 -849.17,7130.61 ; -849.17,7310.18 -793.92,7310.18 -821.54,7254.93 -849.17,7310.18 ; -849.17,7393.06 -835.36,7393.06 -821.54,7379.25 -807.73,7393.06 -793.92,7393.06 -807.73,7406.88 -793.92,7420.69 -807.73,7420.69 -821.54,7434.5 -835.36,7420.69 -849.17,7420.69 -835.36,7406.88 -849.17,7393.06 ; -849.17,7503.57 -849.17,7517.38 -835.36,7531.2 -849.17,7545.01 -849.17,7558.82 -835.36,7558.82 -821.54,7545.01 -807.73,7558.82 -793.92,7558.82 -793.92,7545.01 -807.73,7531.2 -793.92,7517.38 -793.92,7503.57 -807.73,7503.57 -821.54,7517.38 -835.36,7503.57 -849.17,7503.57 ; -849.17,7683.14 -793.92,7683.14 -821.54,7627.89 -849.17,7683.14 ; -838.12,7672.09 -804.97,7672.09 -821.54,7638.94 -838.12,7672.09
  lines w12: -899.26,6720.35 2288.63,6720.35 ; -899.26,7714.91 2288.63,7714.91 ; -561.4,6596.03 -561.4,7839.23 ; -229.23,6596.03 -229.23,7839.23 ; 363.56,6596.03 363.56,7839.23 ; 622.7,6596.03 622.7,7839.23 ; 997.86,6596.03 997.86,7839.23 ; 1722.19,6596.03 1722.19,7839.23 ; -899.26,6596.03 2288.63,6596.03 2288.63,7839.23 -899.26,7839.23 -899.26,6596.03
  text "Symbol" at -824.67,7752.21 h72
  text "Count" at -524.1,7752.21 h72
  text "Hole Size" at -191.94,7752.21 h72
  text "Plated" at 400.86,7752.21 h72
  text "Hole Type" at 660,7752.21 h72
  text "Drill Layer Pair" at 1035.16,7752.21 h72
  text "Hole Tolerance" at 1759.49,7752.21 h72
  text "1375" at -524.1,7627.89 h60
  text "12.00mil (0.305mm)" at -191.94,7627.89 h60
  text "PTH" at 400.86,7627.89 h60
  text "Round" at 660,7627.89 h60
  text "Top Layer - Bottom Layer" at 1035.16,7627.89 h60
  text "1122" at -524.1,7503.57 h60
  text "12.50mil (0.318mm)" at -191.94,7503.57 h60
  text "PTH" at 400.86,7503.57 h60
  text "Round" at 660,7503.57 h60
  text "Top Layer - Bottom Layer" at 1035.16,7503.57 h60
  text "2" at -524.1,7379.25 h60
  text "33.07mil (0.840mm)" at -191.94,7379.25 h60
  text "PTH" at 400.86,7379.25 h60
  text "Round" at 660,7379.25 h60
  text "Top Layer - Bottom Layer" at 1035.16,7379.25 h60
  text "10" at -524.1,7254.93 h60
  text "35.43mil (0.900mm)" at -191.94,7254.93 h60
  text "PTH" at 400.86,7254.93 h60
  text "Round" at 660,7254.93 h60
  text "Top Layer - Bottom Layer" at 1035.16,7254.93 h60
  text "50" at -524.1,7130.61 h60
  text "40.00mil (1.016mm)" at -191.94,7130.61 h60
  text "PTH" at 400.86,7130.61 h60
  text "Round" at 660,7130.61 h60
  text "Top Layer - Bottom Layer" at 1035.16,7130.61 h60
  text "4" at -524.1,7006.29 h60
  text "50.00mil (1.270mm)" at -191.94,7006.29 h60
  text "NPTH" at 400.86,7006.29 h60
  text "Round" at 660,7006.29 h60
  text "Top Layer - Bottom Layer" at 1035.16,7006.29 h60
  text "4" at -524.1,6881.97 h60
  text "125.98mil (3.200mm)" at -191.94,6881.97 h60
  text "PTH" at 400.86,6881.97 h60
  text "Round" at 660,6881.97 h60
  text "Top Layer - Bottom Layer" at 1035.16,6881.97 h60
  text "11" at -524.1,6757.65 h60
  text "270.00mil (6.858mm)" at -191.94,6757.65 h60
  text "PTH" at 400.86,6757.65 h60
  text "Round" at 660,6757.65 h60
  text "Top Layer - Bottom Layer" at 1035.16,6757.65 h60
  text "2578 Total" at -524.1,6633.33 h60
M17 Embedded Cavity:
  text ".Layer_Name" at -153,-843.35 h60
M18 Embedded Assembly:
  text ".Layer_Name" at -153,-843.35 h60
M19 Embedded Keepout:
  text ".Layer_Name" at -153,-843.35 h60

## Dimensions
-80,5830 to -530,0 on M2 Board Dimensions
-470,0 to -160,5830 on M2 Board Dimensions
0,-150 to 6449.68,-146.55 on M2 Board Dimensions
0,0 to 6450,0.14 on M2 Board Dimensions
